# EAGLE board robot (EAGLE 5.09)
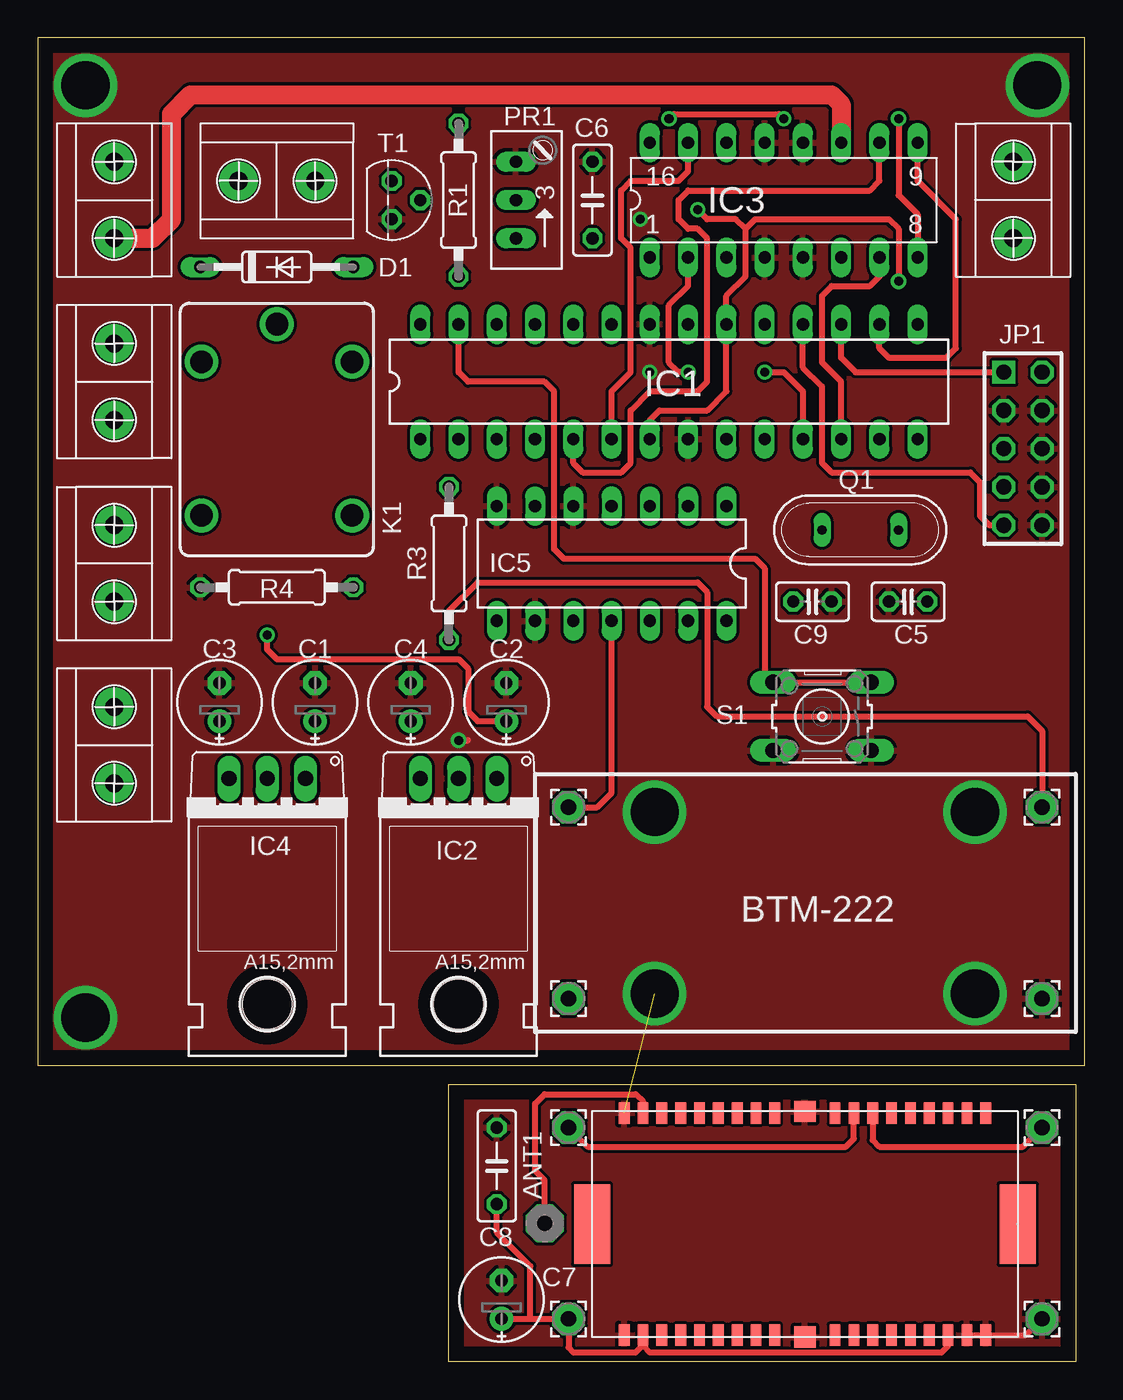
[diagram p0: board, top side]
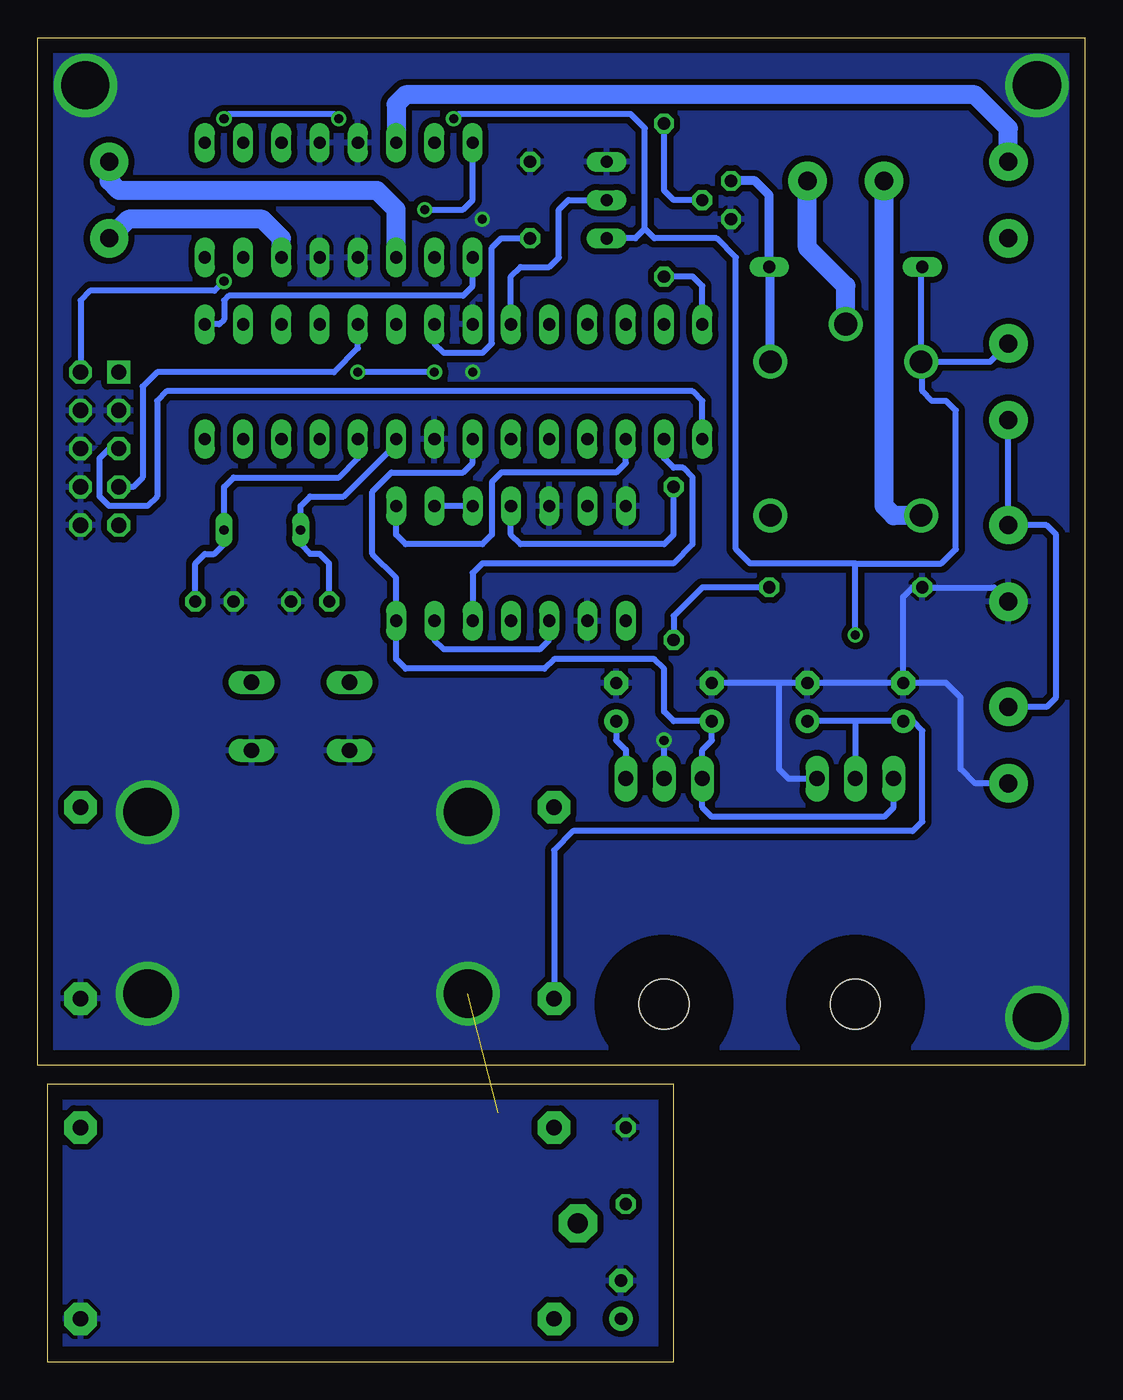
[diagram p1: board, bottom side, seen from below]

Size 69.52 x 87.94 mm. Coordinates in mm from the lower left corner, seen from the top.
Outline: 0,19.69 69.52,19.69 69.52,87.94 0,87.94 0,19.69
Outline: 68.9,18.42 68.9,0 27.3,0 27.3,18.42 68.9,18.42
Copper layers (1*16): Top 0.035mm / dielectric 1.5mm / Bottom 0.035mm
Design rules "default": minimum track width 10mil, minimum drill 24mil, track to track 8mil, track to pad 8mil, pad to pad 8mil, via to via 8mil, smd to smd 8mil, copper to edge 40mil, drill to drill 8mil, minimum pad ring 10mil, minimum via ring 8mil, stop-mask expansion 4mil, vias tented up to drill 0mil, thermal gap 10mil

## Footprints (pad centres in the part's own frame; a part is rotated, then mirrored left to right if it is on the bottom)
PAD-01 = drill 1.321 pad 2.54 octagon: 1 0,0
E2,5-6E = drill 0.813 pad 1.575 round: + -1.27,0 | drill 0.813 pad 1.575 octagon: - 1.27,0
C025-025X050 = drill 0.813 octagon: 1 -1.27,0; 2 1.27,0
C050-025X075 = drill 0.813 octagon: 1 -2.54,0; 2 2.54,0
DO35-10 = drill 0.813 long: A 5.08,0; C -5.08,0
DIL28-3 = drill 0.813 long: 1 -16.51,-3.81; 2 -13.97,-3.81; 3 -11.43,-3.81; 4 -8.89,-3.81; 5 -6.35,-3.81; 6 -3.81,-3.81; 7 -1.27,-3.81; 8 1.27,-3.81; 9 3.81,-3.81; 10 6.35,-3.81; 11 8.89,-3.81; 12 11.43,-3.81; 13 13.97,-3.81; 14 16.51,-3.81; 15 16.51,3.81; 16 13.97,3.81; 17 11.43,3.81; 18 8.89,3.81; 19 6.35,3.81; 20 3.81,3.81; 21 1.27,3.81; 22 -1.27,3.81; 23 -3.81,3.81; 24 -6.35,3.81; 25 -8.89,3.81; 26 -11.43,3.81; 27 -13.97,3.81; 28 -16.51,3.81
TO220V = drill 1.016 long: 1 -2.54,-2.54; 2 0,-2.54; 3 2.54,-2.54
DIP16 = drill 0.813 long: 1 -8.89,-3.81; 2 -6.35,-3.81; 3 -3.81,-3.81; 4 -1.27,-3.81; 5 1.27,-3.81; 6 3.81,-3.81; 7 6.35,-3.81; 8 8.89,-3.81; 9 8.89,3.81; 10 6.35,3.81; 11 3.81,3.81; 12 1.27,3.81; 13 -1.27,3.81; 14 -3.81,3.81; 15 -6.35,3.81; 16 -8.89,3.81
TO220L1 = drill 1.016 long: 1 -2.54,-3.81; 2 0,-3.81; 3 2.54,-3.81 | hole 3.302: 0,11.176
DIL14 = drill 0.813 long: 1 -7.62,-3.81; 2 -5.08,-3.81; 3 -2.54,-3.81; 4 0,-3.81; 5 2.54,-3.81; 6 5.08,-3.81; 7 7.62,-3.81; 8 7.62,3.81; 9 5.08,3.81; 10 2.54,3.81; 11 0,3.81; 12 -2.54,3.81; 13 -5.08,3.81; 14 -7.62,3.81
AVR-ISP-10 = drill 1.016 square: 1 -5.08,-1.27 | drill 1.016 octagon: 2 -5.08,1.27; 3 -2.54,-1.27; 4 -2.54,1.27; 5 0,-1.27; 6 0,1.27; 7 2.54,-1.27; 8 2.54,1.27; 9 5.08,-1.27; 10 5.08,1.27
CQ1 = drill 1.5 round: 1 4.5,-5; 2 4.5,5; C 7,0; NC -5.7,-5; NO -5.7,5
ARK2 = drill 1.2 pad 2.54 round: 1 -2.54,0; 3 2.54,0 | drill 0.8 pad 2.54 round: 2 2.54,0
2,15/1,0 = drill 1.016 pad 2.159 octagon: 1 0,0
RJ9W = drill 0.813 long: A 2.54,0.635; E -2.54,0.635; S 0,0.635
QS = drill 0.61 long: 1 -2.54,0; 2 2.54,0
0207/10 = drill 0.813 octagon: 1 -5.08,0; 2 5.08,0
B3F-10XX = drill 1.016 long: 1 -3.251,2.261; 2 3.251,2.261; 3 -3.251,-2.261; 4 3.251,-2.261
TO92 = drill 0.813 octagon: 1 1.27,0; 2 0,1.905; 3 -1.27,0
BTM-222 = smd 2.4 x 5.3: $AGND -14.625,3.75; $BGND 13.625,3.75 | smd 0.711 x 1.422: P$1 -12.5,-3.625; P$2 -11.25,-3.625; P$3 -10,-3.625; P$4 -8.75,-3.625; P$5 -7.5,-3.625; P$6 -6.25,-3.625; P$7 -5,-3.625; P$8 -3.75,-3.625; P$9 -2.5,-3.625; P$11 1.5,-3.625; P$12 2.75,-3.625; P$13 4,-3.625; P$14 5.25,-3.625; P$15 6.5,-3.625; P$16 7.75,-3.625; P$17 9,-3.625; P$18 10.25,-3.625; P$19 11.5,-3.625; P$20 11.5,11.125; P$21 10.25,11.125; P$22 9,11.125; P$23 7.75,11.125; P$24 6.5,11.125; P$25 5.25,11.125; P$26 4,11.125; P$27 2.75,11.125; P$28 1.5,11.125; P$30 -2.5,11.125; P$31 -3.75,11.125; P$32 -5,11.125; P$33 -6.25,11.125; P$34 -7.5,11.125; P$35 -8.75,11.125; P$36 -10,11.125; P$37 -11.25,11.125; P$38 -12.5,11.125 | smd 1.422 x 1.4: P$10 -0.5,-3.75; P$29 -0.5,11.25

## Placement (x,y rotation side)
ANT1  [PAD-01]  33.66,9.21 0 top
C1  [E2,5-6E]  18.41,43.81 90 top
C2  100uF  [E2,5-6E]  31.12,43.81 90 top
C3  100uF  [E2,5-6E]  12.07,43.81 90 top
C4  [E2,5-6E]  24.77,43.81 90 top
C5  [C025-025X050]  57.79,50.48 180 top
C6  100nF  [C050-025X075]  36.83,77.15 270 top
C7  [E2,5-6E]  30.8,4.13 90 top
C8  100nF  [C050-025X075]  30.48,13.02 270 top
C9  [C025-025X050]  51.44,50.48 180 top
D1  1N4148  [DO35-10]  15.88,72.71 0 top
IC1  MEGA8-P  [DIL28-3]  41.91,65.09 0 top
IC2  LM2940T  [TO220V]  27.94,36.2 180 top
IC3  L293D  [DIP16]  49.53,77.15 0 top
IC4  LD117AV  [TO220L1]  15.24,34.92 180 top
IC5  74HCT14N  [DIL14]  38.1,53.02 180 top
IC6  LD117AV  [TO220L1]  27.94,34.92 180 top
IC7  LM2940T  [TO220V]  15.24,36.2 180 top
JP1  AVR-ISP-10  [AVR-ISP-10]  65.41,60.64 270 top
K1  CQ1-12V  [CQ1]  15.88,61.91 90 top
MOTO1  ARK2  [ARK2]  64.77,77.15 90 top
MOTO2  ARK2  [ARK2]  5.08,77.15 270 top
PAD1  [2,15/1,0]  35.24,36.83 0 top
PAD2  [2,15/1,0]  35.24,15.56 0 top
PAD3  [2,15/1,0]  66.68,15.56 0 top
PAD4  [2,15/1,0]  66.68,36.83 0 top
PAD5  [2,15/1,0]  35.24,2.86 0 top
PAD6  [2,15/1,0]  35.24,24.13 0 top
PAD7  [2,15/1,0]  66.68,2.86 0 top
PAD8  [2,15/1,0]  66.68,24.13 0 top
PR1  20k  [RJ9W]  32.38,77.15 90 top
Q1  8mhz  [QS]  54.61,55.24 180 top
R1  1k  [0207/10]  27.94,77.15 90 top
R3  3,3k  [0207/10]  27.3,53.02 90 top
R4  6,8k  [0207/10]  15.88,51.43 0 top
RELAY  ARK2  [ARK2]  15.88,78.42 0 top
S1  [B3F-10XX]  52.07,42.86 180 top
T1  BC547  [TO92]  23.49,77.15 270 top
U$1  BTM-222_SERIAL  [BTM-222]  51.44,5.4 0 top
U$2  ARK2  [ARK2]  5.08,40.96 270 top
U$3  ARK2  [ARK2]  5.08,53.02 90 top
U$4  ARK2  [ARK2]  5.08,65.09 270 top

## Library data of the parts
ANT1 = discrete
C1-C9 R1 R3 R4 = rcl
D1 = diode
IC1 = atmel
IC2 IC7 = linear
IC3 = ADS
IC4 IC6 = v-reg
IC5 = 74xx-eu
JP1 = avr-4
K1 = relay
MOTO1 MOTO2 RELAY U$2-U$4 = ark2
PAD1-PAD8 = wirepad
PR1 = pot
Q1 = special
S1 = switch-omron
T1 = transistor
U$1 = BTM_222

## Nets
GND: C1.- C2.- C3.- C4.- C5.2 C6.1 C7.- C8.1 C9.1 IC1.8 IC1.22 IC2.2 IC3.4 IC3.5 IC3.12 IC3.13 IC4.1 IC5.5 IC5.7 IC5.9 JP1.3 JP1.4 JP1.6 JP1.8 JP1.10 PAD7.1 PAD8.1 PR1.A R4.1 S1.1 S1.2 T1.1 U$1.P$1 U$1.P$10 U$1.P$18 U$1.P$19 U$1.P$29 U$1.P$38 U$2.2 U$3.1
N$1: IC5.11 PAD1.1
N$2: IC5.10 IC5.13
N$3: C5.1 IC1.10 Q1.1
N$4: C9.2 IC1.9 Q1.2
N$5: IC3.14 MOTO2.1
N$6: IC3.11 MOTO2.2
N$7: IC3.3 MOTO1.2
N$8: IC3.6 MOTO1.1
N$9: IC1.16 IC3.9
N$10: IC1.5 IC3.10
N$11: IC1.6 IC3.15
N$12: IC1.11 IC3.2
N$13: IC1.12 IC3.7
N$14: IC1.17 JP1.1
N$15: IC1.23 PR1.S
N$16: IC1.2 IC5.12
N$17: IC1.19 JP1.7
N$18: IC1.18 JP1.9
N$19: C6.2 IC1.21
N$20: U$2.1 U$3.2 U$4.2
N$21: C2.+ D1.C IC2.1 IC3.8 K1.2 PR1.E U$4.1
N$22: PAD4.1 R3.1 R4.2
N$23: IC5.4 R3.2
N$24: IC5.2 IC5.3
N$25: IC1.3 IC5.1
N$26: IC1.28 R1.1
N$27: IC1.15 IC3.1
N$28: R1.2 T1.2
N$29: ANT1.1 U$1.P$37
N$30: D1.A K1.1 T1.3
N$31: K1.C RELAY.2
N$32: K1.NO RELAY.1
N$33: PAD2.1 U$1.P$27
N$34: PAD3.1 U$1.P$26
N$35: IC1.1 JP1.5
N$36: C7.+ C8.2 PAD5.1 U$1.P$2 U$1.P$17
N$37: IC1.27 S1.3 S1.4
VCC: C4.+ IC1.7 IC1.20 IC2.3 IC3.16 IC4.3 IC5.14 JP1.2
VDD: C1.+ C3.+ IC4.2 PAD6.1

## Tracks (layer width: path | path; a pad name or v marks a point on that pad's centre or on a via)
GND  (via drill 0.6, 3.2)  (1 unrouted)
  Top 0.406: PAD7.1 65.59,1.77 U$1.P$19 U$1.P$18 | v27.94,41.28 28.58,41.28
  Bottom 0.406: U$2.2 7.3,38.42 8.25,39.37 8.25,44.13 9.21,45.09 C3.- | C3.- 12.07,50.8 11.43,51.43 R4.1 6.03,51.43 U$3.1 | C3.- C1.- 20.32,45.09 | 20.32,45.09 C4.- | IC4.1 19.68,38.74 20.32,39.37 20.32,45.09 | IC2.2 v27.94,41.28
  other vias: 40.64,65.72 40.01,75.88 3.18,84.77 66.36,84.77 3.18,22.86 62.23,24.45 40.96,24.45 40.96,36.51 62.23,36.51
  pour Bottom (isolate 0.406): -0.32,88.27 73.66,88.27 73.66,-0.32 -0.32,-0.64
  pour Top: -0.32,88.27 75.56,88.27 75.56,-0.32 -0.32,-0.64
N$1
  Top 0.406: IC5.11 38.1,37.78 37.15,36.83 PAD1.1
N$2
  Bottom 0.406: IC5.10 35.56,47.94 36.2,47.31 42.55,47.31 43.18,47.94 IC5.13
N$3
  Bottom 0.406: IC1.10 48.26,60.01 49.53,58.74 56.51,58.74 57.15,58.1 Q1.1 57.15,54.29 57.79,53.66 58.42,53.66 59.05,53.02 C5.1
N$4
  Bottom 0.406: C9.2 50.16,53.02 50.8,53.66 51.44,53.66 52.07,54.29 Q1.2 52.07,56.83 51.44,57.47 49.21,57.47 45.72,60.96 IC1.9
N$5
  Bottom 1.27: IC3.14 45.72,83.5 45.09,84.14 7.3,84.14 5.08,81.92 MOTO2.1
N$6
  Top 1.27: MOTO2.2 7.62,74.61 8.89,75.88 8.89,82.87 10.16,84.14 52.71,84.14 53.34,83.5 IC3.11
N$7
  Bottom 1.27: MOTO1.2 64.77,78.42 64.13,77.79 46.99,77.79 45.72,76.52 IC3.3
N$8
  Bottom 1.27: IC3.6 53.34,74.61 54.61,75.88 63.5,75.88 MOTO1.1
N$9
  Top 0.406: IC1.16 55.88,67.31 56.51,66.68 60.32,66.68 60.96,67.31 60.96,75.88 58.42,78.42 IC3.9
N$10
  Top 0.406: IC1.5 35.56,59.69 36.2,59.06 38.73,59.06 39.37,59.69 39.37,63.18 40.64,64.45 43.81,64.45 44.45,65.09 44.45,74.61 43.81,75.25 43.18,75.25 42.55,75.88 42.55,77.15 43.18,77.79 55.24,77.79 55.88,78.42 IC3.10
N$11
  Top 0.406: IC1.6 38.1,64.45 39.37,65.72 39.37,73.98 38.73,74.61 38.73,77.79 39.37,78.42 42.55,78.42 43.18,79.06 IC3.15
N$12  (via drill 0.6)
  Top 0.406: IC3.2 43.18,71.44 41.91,70.17 41.91,66.36 42.55,65.72 v43.18,65.72 | v48.26,65.72 49.53,65.72 50.8,64.45 IC1.11
  Bottom 0.406: v43.18,65.72 v48.26,65.72
N$13
  Top 0.406: IC1.12 53.34,65.09 52.07,66.36 52.07,70.8 52.71,71.44 55.24,71.44 55.88,72.07 IC3.7
N$14
  Top 0.406: IC1.17 53.34,66.68 54.29,65.72 JP1.1
N$15
  Bottom 0.406: PR1.S 34.29,77.15 34.92,76.52 34.92,73.34 35.56,72.71 37.47,72.71 38.1,72.07 IC1.23
N$16
  Bottom 0.406: IC1.2 27.94,60.01 27.3,59.37 26.67,59.37 26.04,58.74 26.04,54.29 27.3,53.02 40.01,53.02 40.64,52.39 IC5.12
N$17
  Bottom 0.406: IC1.19 48.26,67.31 49.85,65.72 61.6,65.72 62.55,64.77 62.55,58.74 63.18,58.1 JP1.7
N$18
  Top 0.406: IC1.18 50.8,66.04 52.07,64.77 52.07,59.69 52.71,59.06 61.91,59.06 62.55,58.42 62.55,56.2 63.18,55.56 JP1.9
N$19
  Bottom 0.406: IC1.21 43.18,67.63 42.55,66.99 40.01,66.99 39.37,67.63 39.37,73.98 38.73,74.61 C6.2
N$20
  Bottom 0.406: U$4.2 U$3.2 2.54,55.56 1.91,54.93 1.91,44.13 2.54,43.5 U$2.1
N$21  (via drill 0.6)
  Top 0.406: C2.+ 29.21,42.55 28.58,43.18 28.58,46.04 27.94,46.67 15.88,46.67 15.24,47.31 v15.24,48.26 | v41.91,82.55 42.23,82.87 49.21,82.87 v49.53,82.55 | IC3.8 58.42,76.2 57.15,77.47 v57.15,82.55
  Bottom 0.406: IC2.1 30.48,40.64 31.12,41.28 C2.+ | K1.2 10.88,72.63 D1.C | K1.2 6.3,66.41 U$4.1 | 29.21,75.25 28.58,74.61 24.45,74.61 23.18,73.34 23.18,53.98 22.23,53.02 15.24,53.02 | K1.2 10.8,66.33 10.8,64.45 10.16,63.82 9.21,63.82 8.57,63.18 8.57,53.98 9.52,53.02 15.24,53.02 | v15.24,48.26 15.24,53.02 | PR1.E 29.84,74.61 29.21,75.25 | 29.21,75.25 29.21,81.92 30.16,82.87 41.59,82.87 v41.91,82.55 | v49.53,82.55 49.85,82.87 56.83,82.87 v57.15,82.55
N$22
  Top 0.406: R3.1 27.3,49.85 29.21,51.75 43.81,51.75 44.45,51.12 44.45,43.5 45.09,42.86 65.72,42.86 66.68,41.91 PAD4.1
  Bottom 0.406: R3.1 27.3,49.53 25.4,51.43 R4.2
N$23
  Bottom 0.406: R3.2 27.3,54.93 27.94,54.29 37.47,54.29 38.1,54.93 IC5.4
N$24
  Bottom 0.406: IC5.3 IC5.2
N$25
  Bottom 0.406: IC1.3 30.48,59.69 31.12,59.06 38.73,59.06 39.37,58.42 39.37,54.93 40.01,54.29 45.09,54.29 45.72,54.93 IC5.1
N$26
  Bottom 0.406: IC1.28 25.4,71.44 26.04,72.07 R1.1
N$27
  Bottom 0.406: IC3.1 40.64,71.44 41.27,70.8 56.83,70.8 57.15,70.48 57.15,69.21 57.47,68.9 IC1.15
N$28
  Bottom 0.406: R1.2 27.94,77.79 27.3,77.15 T1.2
N$29
  Top 0.406: ANT1.1 33.66,12.06 33.02,12.7 33.02,17.14 33.66,17.78 39.69,17.78 40.19,17.28 U$1.P$37
N$30
  Bottom 0.61: K1.1 20.88,72.63 D1.A 20.95,77.47 21.91,78.42 T1.3
N$31
  Bottom 1.27: K1.C 15.88,71.44 18.41,73.98 RELAY.2
N$32
  Bottom 1.27: RELAY.1 13.34,56.83 12.7,56.2 10.89,56.2 K1.NO
N$33
  Top 0.406: U$1.P$27 54.18,14.81 53.66,14.29 36.51,14.29 PAD2.1
N$34
  Top 0.406: U$1.P$26 55.43,14.73 55.88,14.29 65.41,14.29 PAD3.1
N$35
  Bottom 0.406: IC1.1 25.4,63.82 26.04,64.45 60.96,64.45 61.6,63.82 61.6,57.47 62.23,56.83 64.77,56.83 65.41,57.47 65.41,60.01 64.77,60.64 JP1.5
N$36
  Top 0.406: 32.7,2.86 PAD5.1 35.24,0.95 35.56,0.63 39.69,0.63 40.19,1.13 | 40.19,1.13 40.19,1.09 40.64,0.63 60.01,0.63 60.43,1.06 U$1.P$17 | 40.19,1.13 U$1.P$2 | C7.+ 32.7,2.86 | 32.7,2.86 32.7,6.35 30.48,8.57 C8.2
N$37
  Top 0.406: IC1.27 27.94,65.72 28.58,65.09 33.66,65.09 34.29,64.45 34.29,53.98 34.92,53.34 47.62,53.34 48.26,52.7 48.26,45.72 48.9,45.09 48.9,45.2 S1.4 S1.3
VCC  (via drill 0.6)
  Top 0.406: IC1.7 40.64,62.55 41.27,63.18 44.45,63.18 45.72,64.45 IC1.20 45.72,70.8 46.99,72.07 46.99,75.25 | 46.99,75.25 47.62,75.88 56.51,75.88 57.15,75.25 v57.15,71.76 | 46.99,75.25 46.35,75.88 44.45,75.88 v43.81,76.52
  Bottom 0.406: IC4.3 12.7,36.83 13.34,36.2 24.77,36.2 25.4,36.83 IC2.3 25.4,40.64 24.77,41.28 C4.+ 27.3,42.55 27.94,43.18 27.94,46.04 28.58,46.67 35.24,46.67 35.88,46.04 45.09,46.04 45.72,46.67 IC5.14 45.72,52.07 47.31,53.66 47.31,57.78 46.04,59.06 41.27,59.06 40.64,59.69 IC1.7 | v43.81,76.52 41.27,76.52 40.64,77.15 IC3.16 | JP1.2 66.68,70.48 66.04,71.12 57.79,71.12 v57.15,71.76
VDD
  Bottom 0.406: 15.24,42.55 C3.+ 11.43,42.55 10.8,41.91 10.8,35.88 11.43,35.24 33.97,35.24 35.24,33.97 PAD6.1 | 15.24,42.55 C1.+ | 15.24,42.55 IC4.2

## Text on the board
tPlace: BTM-222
